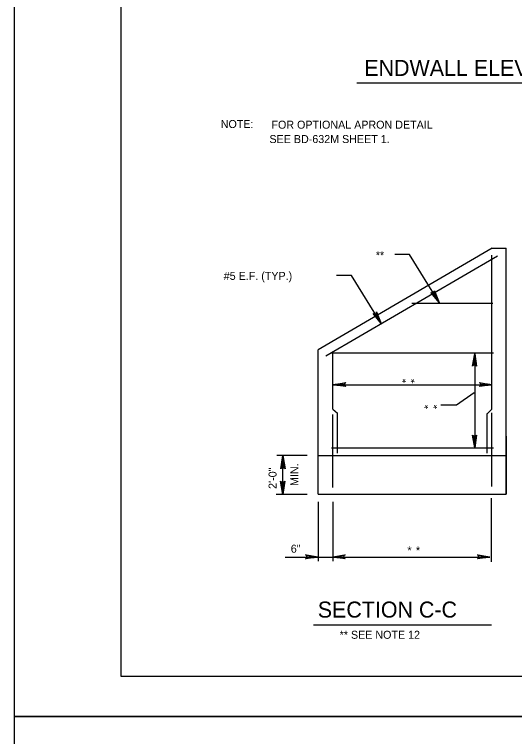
# Model space of a CAD drawing. Extents: x 639011 to 639866, y 298840 to 300028.
# Drawn here: x 639011.3 to 639198.6, y 299426.3 to 299696.8 of the extents above; entities that cross this region are included whole.
import ezdxf

# ---------------------------------------------------------------- set-up
doc = ezdxf.new("R2010")
doc.units = 0
doc.layers.add('2', color=7, linetype='Continuous')
doc.layers.add('PLT-BNDY', color=7, linetype='Continuous')

msp = doc.modelspace()

# ---------------------------------------------------------------- linework, layer by layer
at = {"layer": '2'}
for p, q in [((639051.26, 299448.83), (639051.26, 300012.83)), ((639139.55, 299671.18), (639243.97, 299671.18)), ((639190.24, 299609.28), (639125.05, 299571.22)), ((639190.24, 299609.28), (639195.49, 299609.28)), ((639195.49, 299517.19), (639195.49, 299609.28)), ((639192.21, 299606.22), (639127.9, 299568.82)), ((639159.18, 299606.88), (639153.72, 299606.88)), ((639170.33, 299588.94), (639159.18, 299606.88)), ((639190.02, 299553.72), (639190.02, 299606.66)), ((639137.52, 299599), (639131.92, 299599)), ((639148.68, 299581.07), (639137.52, 299599)), ((639160.05, 299588.72), (639190.46, 299588.72)), ((639125.05, 299517.19), (639125.05, 299571.22)), ((639130.08, 299570.13), (639190.68, 299570.13)), ((639130.52, 299553.94), (639130.52, 299570.57)), ((639183.68, 299569.69), (639183.68, 299534.47)), ((639130.52, 299558.1), (639190.24, 299558.1)), ((639130.52, 299548.91), (639130.52, 299555.03)), ((639183.46, 299555.03), (639176.9, 299550.44)), ((639190.02, 299548.91), (639190.02, 299555.03)), ((639130.52, 299548.91), (639132.31, 299547.48)), ((639176.9, 299550.44), (639170.99, 299550.44)), ((639190.02, 299548.91), (639188.22, 299547.11)), ((639130.52, 299519.6), (639130.52, 299546.94)), ((639132.27, 299532.5), (639132.27, 299547.47)), ((639188.27, 299532.5), (639188.27, 299547.31)), ((639190.02, 299520.03), (639190.02, 299547.6)), ((639195.49, 299538.85), (639195.49, 299517.19)), ((639130.08, 299534.47), (639190.68, 299534.47)), ((639120.96, 299531.63), (639109.6, 299531.63)), ((639111, 299526.57), (639111.78, 299531.63)), ((639111.78, 299531.63), (639111.21, 299526.83)), ((639111.56, 299527.01), (639111.78, 299531.63)), ((639111.78, 299516.97), (639111.78, 299531.63)), ((639111.78, 299531.63), (639112.04, 299527.01)), ((639112.39, 299526.84), (639111.78, 299531.63)), ((639111.78, 299531.63), (639112.63, 299526.58)), ((639111.78, 299531.63), (639111.8, 299527.01)), ((639125.05, 299531.63), (639195.71, 299531.63)), ((639111.21, 299526.83), (639111, 299526.57)), ((639111.21, 299526.83), (639111.56, 299527.01)), ((639111.56, 299527.01), (639112.04, 299527.01)), ((639112.04, 299527.01), (639112.39, 299526.84)), ((639112.63, 299526.58), (639112.39, 299526.84)), ((639111.78, 299516.97), (639110.94, 299522.02)), ((639110.94, 299522.02), (639111.17, 299521.76)), ((639111.52, 299521.59), (639111.17, 299521.76)), ((639111.17, 299521.76), (639111.78, 299516.97)), ((639111.78, 299516.97), (639111.52, 299521.59)), ((639112, 299521.59), (639111.52, 299521.59)), ((639111.78, 299516.97), (639111.76, 299521.59)), ((639112.57, 299522.03), (639111.78, 299516.97)), ((639111.78, 299516.97), (639112.35, 299521.77)), ((639112, 299521.59), (639111.78, 299516.97)), ((639112.35, 299521.77), (639112, 299521.59)), ((639112.35, 299521.77), (639112.57, 299522.03)), ((639120.96, 299516.97), (639109.31, 299516.97)), ((639125.05, 299517.19), (639195.49, 299517.19)), ((639125.05, 299514.29), (639125.05, 299492.03)), ((639130.52, 299514.29), (639130.52, 299492.03)), ((639189.8, 299515.66), (639189.8, 299491.82)), ((639189.8, 299514.29), (639189.8, 299491.82)), ((639112.68, 299493.57), (639125.05, 299493.57)), ((639125.05, 299493.57), (639130.52, 299493.57)), ((639130.52, 299493.57), (639189.37, 299493.57)), ((639190.01, 299468.03), (639123.26, 299468.03)), ((639837.26, 299448.83), (639051.26, 299448.83))]:
    msp.add_line(p, q, dxfattribs=at)
for points in [[(639168.37, 299593.1), (639168.37, 299592.88), (639170.33, 299588.94), (639168.37, 299593.1), (639168.58, 299593.32), (639170.33, 299588.94), (639167.93, 299592.44), (639167.49, 299592.44), (639170.33, 299588.94), (639167.27, 299592.66), (639167.49, 299592.44)], [(639168.37, 299593.1), (639168.37, 299592.88), (639170.33, 299588.94), (639168.37, 299593.1), (639168.58, 299593.32), (639170.33, 299588.94), (639167.93, 299592.44), (639167.49, 299592.44), (639170.33, 299588.94), (639167.27, 299592.66), (639167.49, 299592.44)], [(639168.37, 299593.1), (639168.37, 299592.88), (639170.33, 299588.94), (639168.37, 299593.1), (639168.58, 299593.32), (639170.33, 299588.94), (639167.93, 299592.44), (639167.49, 299592.44), (639170.33, 299588.94), (639167.27, 299592.66), (639167.49, 299592.44)], [(639146.93, 299585.22), (639146.71, 299585), (639148.68, 299581.07), (639146.93, 299585.22), (639146.93, 299585.44), (639148.68, 299581.07), (639146.27, 299584.57), (639145.83, 299584.57), (639148.68, 299581.07), (639145.62, 299584.78), (639145.83, 299584.57)], [(639146.93, 299585.22), (639146.71, 299585), (639148.68, 299581.07), (639146.93, 299585.22), (639146.93, 299585.44), (639148.68, 299581.07), (639146.27, 299584.57), (639145.83, 299584.57), (639148.68, 299581.07), (639145.62, 299584.78), (639145.83, 299584.57)], [(639146.93, 299585.22), (639146.71, 299585), (639148.68, 299581.07), (639146.93, 299585.22), (639146.93, 299585.44), (639148.68, 299581.07), (639146.27, 299584.57), (639145.83, 299584.57), (639148.68, 299581.07), (639145.62, 299584.78), (639145.83, 299584.57)], [(639183.02, 299565.32), (639183.46, 299565.53), (639183.68, 299569.69), (639183.02, 299565.32), (639182.8, 299565.1), (639183.68, 299569.69), (639183.9, 299565.53), (639184.12, 299565.32), (639183.68, 299569.69), (639184.33, 299565.1), (639184.12, 299565.32)], [(639135.12, 299557.66), (639134.9, 299557.88), (639130.52, 299558.1), (639135.12, 299557.66), (639135.33, 299557.44), (639130.52, 299558.1), (639134.9, 299558.32), (639135.12, 299558.75), (639130.52, 299558.1), (639135.33, 299558.97), (639135.12, 299558.75)], [(639135.12, 299557.66), (639134.9, 299557.88), (639130.52, 299558.1), (639135.12, 299557.66), (639135.33, 299557.44), (639130.52, 299558.1), (639134.9, 299558.32), (639135.12, 299558.75), (639130.52, 299558.1), (639135.33, 299558.97), (639135.12, 299558.75)], [(639135.12, 299557.66), (639134.9, 299557.88), (639130.52, 299558.1), (639135.12, 299557.66), (639135.33, 299557.44), (639130.52, 299558.1), (639134.9, 299558.32), (639135.12, 299558.75), (639130.52, 299558.1), (639135.33, 299558.97), (639135.12, 299558.75)], [(639135.12, 299557.66), (639134.9, 299557.88), (639130.52, 299558.1), (639135.12, 299557.66), (639135.33, 299557.44), (639130.52, 299558.1), (639134.9, 299558.32), (639135.12, 299558.75), (639130.52, 299558.1), (639135.33, 299558.97), (639135.12, 299558.75)], [(639185.65, 299558.75), (639185.87, 299558.32), (639190.24, 299558.1), (639185.65, 299558.75), (639185.43, 299558.97), (639190.24, 299558.1), (639185.87, 299557.88), (639185.65, 299557.66), (639190.24, 299558.1), (639185.43, 299557.44), (639185.65, 299557.66)], [(639184.12, 299539.07), (639183.9, 299538.85), (639183.68, 299534.47), (639184.12, 299539.07), (639184.33, 299539.28), (639183.68, 299534.47), (639183.46, 299538.85), (639183.02, 299539.07), (639183.68, 299534.47), (639182.8, 299539.28), (639183.02, 299539.07)], [(639120.68, 299494.22), (639120.68, 299493.78), (639125.05, 299493.57), (639120.68, 299494.22), (639120.24, 299494.44), (639125.05, 299493.57), (639120.68, 299493.35), (639120.68, 299493.13), (639125.05, 299493.57), (639120.24, 299492.91), (639120.68, 299493.13)], [(639134.9, 299493.13), (639134.68, 299493.35), (639130.52, 299493.57), (639134.9, 299493.13), (639135.12, 299492.91), (639130.52, 299493.57), (639134.68, 299493.78), (639134.9, 299494.22), (639130.52, 299493.57), (639135.12, 299494.44), (639134.9, 299494.22)], [(639184.99, 299494.22), (639184.99, 299493.78), (639189.37, 299493.57), (639184.99, 299494.22), (639184.77, 299494.44), (639189.37, 299493.57), (639184.99, 299493.35), (639184.99, 299493.13), (639189.37, 299493.57), (639184.77, 299492.91), (639184.99, 299493.13)], [(639184.99, 299494.22), (639184.99, 299493.78), (639189.37, 299493.57), (639184.99, 299494.22), (639184.77, 299494.44), (639189.37, 299493.57), (639184.99, 299493.35), (639184.99, 299493.13), (639189.37, 299493.57), (639184.77, 299492.91), (639184.99, 299493.13)], [(639184.99, 299494.22), (639184.99, 299493.78), (639189.37, 299493.57), (639184.99, 299494.22), (639184.77, 299494.44), (639189.37, 299493.57), (639184.99, 299493.35), (639184.99, 299493.13), (639189.37, 299493.57), (639184.77, 299492.91), (639184.99, 299493.13)]]:
    msp.add_lwpolyline(points, dxfattribs=at)
at = {"layer": 'PLT-BNDY'}
for points in [[(639011.26, 300027.83), (639852.26, 300027.83), (639852.26, 299433.83), (639011.26, 299433.83)], [(639011.26, 299433.83), (639852.26, 299433.83), (639852.26, 298839.83), (639011.26, 298839.83)]]:
    msp.add_lwpolyline(points, close=True, dxfattribs=at)

# ---------------------------------------------------------------- texts
at = {"layer": '2'}
for s, height, p in [('ENDWALL ELEVATION', 6, (639142.31, 299673.8)), ('NOTE:', 3, (639088.53, 299654.28)), ('FOR OPTIONAL APRON DETAIL', 3, (639107.53, 299654.03)), ('SEE BD-632M SHEET 1.', 3, (639106.78, 299648.65)), ('**', 3, (639146.63, 299605.15)), ('#5 E.F. (TYP.)', 3, (639089.66, 299597.4)), ('6"', 3, (639114.77, 299495.2)), ('*', 3, (639158.46, 299494.57)), ('*', 3, (639161.63, 299494.57)), ('SECTION C-C', 6, (639124.88, 299470.9)), ('** SEE NOTE 12', 3, (639133.07, 299462.96))]:
    msp.add_text(s, height=height, dxfattribs=at).set_placement(p)
for s, rotation, p in [('*', 180, (639157.98, 299561.72)), ('*', 180, (639161.2, 299561.65)), ('*', 180, (639166.31, 299552.02)), ('*', 180, (639169.66, 299552.02)), ('2\'-0"', 90, (639109.45, 299519.11)), ('MIN.', 90, (639117.59, 299520.19))]:
    msp.add_text(s, height=3, rotation=rotation, dxfattribs=at).set_placement(p)

doc.saveas('drawing.dxf')
